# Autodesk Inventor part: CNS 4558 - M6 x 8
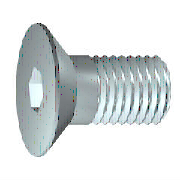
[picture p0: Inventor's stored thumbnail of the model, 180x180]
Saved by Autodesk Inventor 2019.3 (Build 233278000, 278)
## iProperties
Created: 2018-01
Part Number: CNS 4558 - M6 x 8
Material: Ocel, měkká
Description: Šroub se zápustnou hlavou
Document SubType Name: Modeling
Standard: CNS 4558
Designer: B-hon
Standards Organization: CNS
Language: cs-CZ
Size Designation: M6 x 8
Categories: <MemberInstance><Categories><Category DisplayName="Spojovací materiál" InternalName="e4da775c-781d-43d5-af7c-5136215cf5a6" Mnemonic="FSTN"><Category DisplayName
Density: 7.85 g/cm^3
Appearance: Pololeštěná
IsCustomPart: 0
Author: B-hon
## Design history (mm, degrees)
body "Solid1"
revolve "Těleso" stored, may be unused: angle "d13" = 90 deg
sketch "Náčrt2"
  geometry: L1 (0, -8.4)-(0, 8.4) reference; L2 (-8.4, 0)-(8.4, 0) reference; L3 (2.309, 0)-(1.155, -2); L4 (1.155, -2)-(-1.155, -2); L5 (-1.155, -2)-(-2.309, 0); L6 (-2.309, 0)-(-1.155, 2); L7 (-1.155, 2)-(1.155, 2); L8 (1.155, 2)-(2.309, 0); A1 r 2.309 centre (0, 0) between (0, 2.309) and (2.309, 0) reference; 2 further points
  constraints: 12 end point, 2 coincident, 2 point on circle, 2 point on line, 12 other
extrude "Drážka" join sketch "Náčrt2" taper "d14" = 0 deg; stored distance "d30" = 10
feature "Závit" dims "d15" = 1.7 (= GEL), "d16" = 0
chamfer "Zkosení1" distance "d17" = 0.61345 (= -0.5 x SPD + 0.5 x GD); stored, may be unused: second distance "d18" = 0.61345 (= GUL), angle "d39" = 45 deg
workplane "Work Plane1"
sketch "Náčrt1"
  geometry: L1 (8, 0)-(8, 3); L2 (8, 3)-(6.3, 3); L3 (6.3, 3)-(5.687, 3); L4 (0, 6)-(0, 2.309); L5 (0, 2.309)-(2.5, 2.309); L6 (2.5, 2.309)-(3.833, 0); L7 (3.833, 0)-(8, 0); L8 (0, 6)-(0.3, 6); L9 (0.3, 6)-(3.3, 3); L10 (5.687, 3)-(3.3, 3); L11 (6.3, 3)-(3.3, 3); L12 (3.3, 3)-(3.3, 3); L13 (-1.6, 0)-(9.6, 0) reference; L14 (0, -1.2)-(0, 7.2) reference
  constraints: 24 end point, 4 collinear, 3 parallel
  dimensions: "d0" = 8 distance between parallel lines of L4 L1 (= NLG); "d1" = 1.7 distance from line of L2.end L1 (= GEL); "d2" = 2.5 distance from line of L5.end L4 (= INTI); "d3" = 6 diameter of L2 L7 (= GD); "d6" = 3.3 distance from line of L9.end L4 (= KOH); "d7" = 45 deg angle of L9 L7 (= 0.5 x SEWI); "d8" = 4.6188 diameter of L5 L7 (= 1.1547 x SW); "d9" = 60 deg angle of L6 L7; "d10" = 12 diameter of L8 L7 (= KOD); "d11" = 6 diameter of L10 L7 (= BDM); "d12" = 0.61345 distance of L3.end L2.end (= GAL)
other parameters: "NLG" = 8 [user parameter; used in 1 equation term], "INTI" = 2.5 [user parameter; used in 1 equation term], "GEL" = 1.7 [user parameter; used in 2 equation terms], "GAL" = 0.61345 (= 0.61345 x PTC) [user parameter; used in 1 equation term], "KOH" = 3.3 [user parameter; used in 1 equation term], "KOD" = 12 [user parameter; used in 1 equation term], "GUL" = 0.61345 (= 0.61345 x PTC) [user parameter; used in 1 equation term], "SPD" = 4.7731 (= NND - 1.2269 x PTC) [user parameter; used in 1 equation term], "BDM" = 6 (= NND) [user parameter; used in 1 equation term], "GD" = 6 (= NND) [user parameter; used in 2 equation terms], "SEWI" = 90 deg [user parameter; used in 1 equation term], "d20" = 0, "SW" = 4 [user parameter; used in 2 equation terms], "d43" = 0, "d44" = 0, "TOA" = 30 deg [user parameter], "GD1" = 4.7731 (= THREADDIA - 1.2269 x PTC) [user parameter], "EPV" = 6.3 [user parameter], "THREADDIA" = 6 [user parameter; used in 1 equation term], "PTC" = 1 [user parameter; used in 5 equation terms], "NND" = 6 [user parameter; used in 3 equation terms], "E0" = 4.62 (= 1.155 x SW) [user parameter]
